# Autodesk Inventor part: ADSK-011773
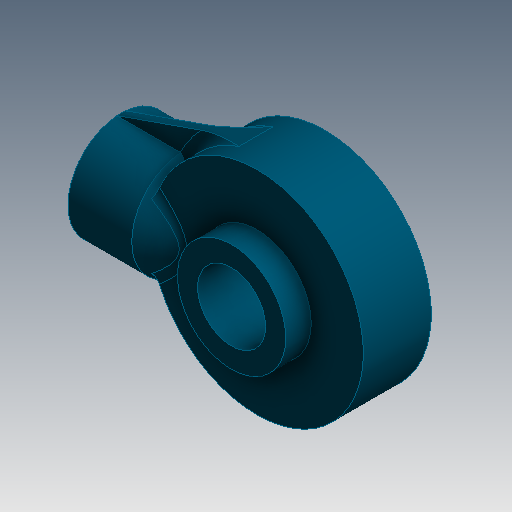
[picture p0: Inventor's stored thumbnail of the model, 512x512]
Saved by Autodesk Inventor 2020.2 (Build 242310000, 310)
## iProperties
Created: 1999-12
Part Number: ADSK-011773
Description: BRNG,HANGER,1.00B
Document SubType Name: Modeling
Designer: tgregory
Material: Générique
Density: 1 g/cm^3
Appearance: Bearing Blue
Mass: 147.682 g
Surface Area: 257.245 cm^2
Volume: 147.682 cm^3
Control State: 0
Checked Out: False
Last Check In By: sspink
Last Check In Date: 1999-12-22
Master: False
Shininess: 0.0
Length Units: 11272
Angle Units: 11279
Time Units: 11290
Mass Units: 11286
Length Display Precision: 3
Angle Display Precision: 2
Compacted: True
Dimensions: 3,1x1,7x4,1 in
Mass: 0,326 lb
VLT_Material: Generic
Density: 0.0
Volumn: 0.0
Area: 0.0
PropertySet Name: Model Information
Author: tgregory
Revision Number: -
Title: BRNG,HANGER,1.00B
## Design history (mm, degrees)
node "Extrusion1" dims "d1" = 38.1, "d2" = 0
node "Extrusion2" dims "d4" = 9.525, "d5" = 0
node "Extrusion3" dims "d7" = 3.175, "d8" = 0
node "Hole1" dims "d9" = 25.4, "d10" = 9.525, "d11" = 6.35, "d12" = 60 deg, "d13" = 19.05, "d14" = 118 deg
workplane "Work Plane1"
workaxis "Work Axis1"
node "Extrusion4" dims "d15" = 23.8125, "d16" = 0
workplane "Work Plane5"
workplane "Work Plane6"
workplane "Work Plane8"
workplane "Work Plane9"
node "Extrusion5" dims "d20" = 3.175, "d21" = 0
node "Extrusion7" dims "d24" = 19.05, "d25" = -30 deg
node "Fillet3" dims "d28" = 4.7625
node "Fillet4" dims "d29" = 4.7625
node "Fillet5" dims "d30" = 4.7625
node "Hole2" dims "d31" = 23.0886, "d32" = 9.525, "d33" = 6.35, "d34" = 60 deg, "d35" = 19.05, "d36" = 118 deg
node "Solide1"
node "Corps solides"
node "Corps surfaciques"
sketch "Sketch1"
  geometry: C1 r 39.688 at (0, 0); 1 further point
  constraints: 1 centre point, 1 coincident
  dimensions: "d0" = 79.375 diameter of C1
sketch "Sketch2"
  geometry: C1 r 39.688 at (0, 0) reference; C2 r 20.241 at (0, 0)
  constraints: 1 centre point, 1 coincident
  dimensions: "d3" = 40.48125 diameter of C2
sketch "Sketch3"
  geometry: C1 r 39.688 at (0, 0) reference; C2 r 20.241 at (0, 0)
  constraints: 1 centre point, 1 coincident
  dimensions: "d6" = 40.48125 diameter of C2
sketch "Sketch4"
  geometry: C1 r 20.241 at (0, 0) reference; 1 further point
  constraints: 1 coincident
sketch "Sketch5"
  geometry: L1 (39.688, -9.525)-(39.688, -34.925) reference; L2 (39.688, -34.925)-(-39.687, -34.925) reference; C1 r 19.844 at (0, -22.225)
  constraints: 1 centre point
  dimensions: "d37" = 39.6875 diameter of C1; "d42" = 12.7 distance from line of C1.centre L2; "d43" = 39.6875 distance from line of C1.centre L1 (= 0.5 x d0)
sketch "Sketch7"
  geometry: L1 (-63.5, -19.844)-(-63.5, 19.844) reference; L2 (-63.5, -19.844)-(-13.097, -37.464); L3 (-63.5, 19.844)-(-13.097, 37.464); L4 (-39.688, 19.844)-(-39.688, -19.844) reference; L5 (-73.819, -19.844)-(70.644, -19.844) reference; L6 (-39.688, 19.844)-(-63.5, 19.844) reference; L7 (-13.097, 37.464)-(-13.097, -37.464); A1 r 39.688 centre (0, 0) between (-39.687, 0) and (-13.097, -37.464) reference
  constraints: 6 end point, 2 point on circle, 2 tangent
sketch "Sketch9"
  geometry: C1 r 19.844 at (22.225, 0); A1 r 19.844 centre (22.225, 0) between (23.812, -19.78) and (23.812, 19.78) reference
  constraints: 1 centre point, 1 coincident
  dimensions: "d44" = 39.6875 diameter of C1 (= d37)
sketch "Sketch10"
  geometry: A1 r 19.844 centre (-22.225, 0) between (-20.637, -19.78) and (-20.637, 19.78) reference; 1 further point
  constraints: 1 coincident
other parameters: "d18" = 0, "d19" = -22.225
